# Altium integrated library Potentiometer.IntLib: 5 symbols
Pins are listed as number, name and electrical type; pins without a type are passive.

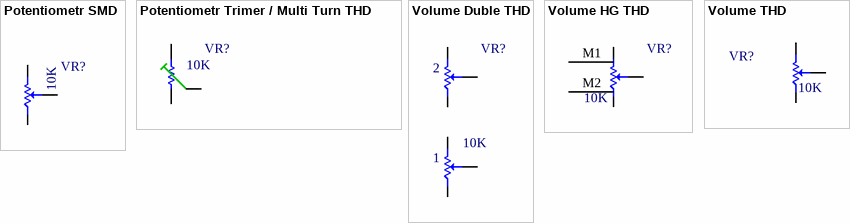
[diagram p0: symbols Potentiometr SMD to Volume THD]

## Potentiometr SMD
designator VR?  value 10K
Potentiometr SMD
footprint POT4MM-Small Pot (Square Trimming Potentiometer)
footprint POT4MM-Triming (Square Trimming Potentiometer)
footprint SMD_PVG3A
footprint SMD_PVG5H
footprint SMD_PVZ3A
footprint SMD_SM-42/43B
footprint SMD_SM-42/43W
footprint POTS_V10MM (POT, TRIM, V-10 10mm SMD)
footprint POTS_3314G (POT SMD, 5.0X5.0mm, Trimming, 3314G)
footprint POTS_3214W (POT SMD, 4.0X5.0mm, Trimming SM-42/43W 3214W)
footprint POTS_5MM (POT SMD, 5.0X5.0mm, Trimming PVG5H)
footprint POTS_3MM (POT SMD, 3.0X3.0mm, Trimming PVG3A PVZ3A)
pins: 1 CCW, 2, 3

## Potentiometr Trimer / Multi Turn THD
designator VR?  value 10K
Potentiometr Trimer / Multi Turn THD
footprint POT_V10MM (POT, TRIM, V-10 10mm)
footprint POT_PIHER15MM (POT, TRIM, PIHER PT-15 15mm)
footprint POT_PIHER10MM (POT, TRIM, PIHER PT-10 10mm)
footprint POT_CA9MTV (POT, TRIM, 10.0X10.0mm, CA9MTV)
footprint POT_3362S (POT, TRIM, 4.3X6.6mm 3362S)
footprint POT_3362H (POT, TRIM, 6.6X6.8mm 3362H, 3362P, 3362R)
footprint S64Y
footprint S64W
footprint POT_3306W (POT, TRIM, 4.5X6.8mm 3306W)
footprint POT_3306F (POT, TRIM, 7.0X7.0mm, pitch: 2.5mm, MURATA, 3306F)
footprint POT_3296Z (POT, TRIM, 10.0X5.0mm, pitch: 2.5mm, 3296Z)
footprint POT_3296Y (POT, TRIM, 10.0X5.0mm, pitch: 2.5mm, MURATA, PV36Y 3296Y S64Y)
footprint POT_3296X (POT, TRIM, 10.0X5.0mm, pitch: 2.5mm, MURATA, PV36X 3296X)
footprint POT_3296W (POT, TRIM, 10.0X5.0mm, pitch: 2.5mm 3299W 3296W S64W)
footprint POT_3296P (POT, TRIM, 9.5X9.5mm HORIZENTAL 3296P)
footprint POT_3262W (POT, TRIM, 4.3X6.6mm 3262W)
footprint POT_3260H (POT, TRIM, 4.3X6.3mm 3260H)
footprint POT_3006P (POT, TRIM, 19.0X4.8mm 3006P)
footprint POT_7X5 (POT, TRIM, 7.5X5.0mm, pitch: 5.0mm)
footprint Pot 00
footprint Multi Turn 02
footprint Multi Turn 01 (Stand Multi Turn - Turning CW Increase P1~2 Resistor)
footprint CA9V
footprint CA9MTV
footprint CA9H5
footprint 3306W
footprint 3306F
footprint 3296Z
footprint 3296Y
footprint 3296X
footprint 3296W
footprint 3296P
footprint 3006P
pins: 1, 2, 3

## Volume Duble THD
designator VR?  value 10K
Volume Duble THD
footprint 3RP/1610G
pins: 1-1, 1-2, 1-3, 2-1, 2-2, 2-3

## Volume HG THD
designator VR?  value 10K
Volume HG THD
footprint EVUF
pins: 1, 2, 3, M1, M2

## Volume THD
designator VR?  value 10K
Volume THD
footprint Setpoint POT
footprint Setpoint POT Right
footprint VOL_R (VOULME RIGHT ANGLE)
footprint VOL_3590S (VOULME 3590S)
footprint VOL_14MM (VOULME  14mm, RV141F-40E3)
footprint VOL_9MM (VOULME  9mm Alpha Alps, RV09ACF EVUF)
footprint VOL_R S (VOULME RIGHT ANGLE (www.Smartw.ir))
footprint Setpoint POT Right S ((www.Smartw.ir))
pins: 1, 2, 3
